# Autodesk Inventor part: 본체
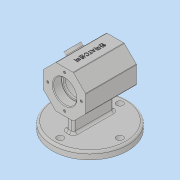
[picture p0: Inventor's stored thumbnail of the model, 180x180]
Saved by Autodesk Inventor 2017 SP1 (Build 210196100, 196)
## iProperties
Part Number: 본체
Material: 일반
Document SubType Name: Modeling
Designer: 00-00
Density: 1 g/cm^3
Appearance: 기본값
Author: 00-00
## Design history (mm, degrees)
sketch "스케치1" dims "d0" = 58
  geometry: L1 (12.012, 29)-(29, 12.012); L2 (29, 12.012)-(29, -12.012); L3 (29, -12.012)-(12.012, -29); L4 (12.012, -29)-(-12.012, -29); L5 (-12.012, -29)-(-29, -12.012); L6 (-29, -12.012)-(-29, 12.012); L7 (-29, 12.012)-(-12.012, 29); L8 (-12.012, 29)-(12.012, 29); 4 further points
  constraints: 16 end point, 2 coincident, 2 vertical alignment, 1 midpoint, 19 other
extrude "돌출1" new body sketch "스케치1" stored distance "d1" = 70; taper "d2" = 0 deg
sketch "스케치2"
  geometry: L1 (29, -35)-(-29, -35) reference; L2 (-29, -35)-(-29, 35) reference; L3 (-29, 35)-(29, 35) reference; L4 (29, 35)-(29, -35) reference; L5 (0, 35)-(16, 35); L6 (16, 35)-(16, 23); L7 (16, 23)-(0, 23); L8 (0, 23)-(0, 35); L9 (0, 23)-(14, 23); L10 (14, 23)-(14, 20); L11 (14, 20)-(0, 20); L12 (0, 20)-(0, 23); L13 (0, 20)-(22, 20); L14 (22, 20)-(22, -20); L15 (22, -20)-(0, -20); L16 (0, -20)-(0, 20); L17 (0, -20)-(14, -20); L18 (14, -20)-(14, -23); L19 (14, -23)-(0, -23); L20 (0, -23)-(0, -20); L21 (0, -23)-(16, -23); L22 (16, -23)-(16, -35); L23 (16, -35)-(0, -35); L24 (0, -35)-(0, -23); 2 further points
  constraints: 40 end point, 10 parallel, 5 horizontal, 5 perpendicular, 2 midpoint, 1 horizontal alignment, 1 point on line
  dimensions: "d3" = 32 diameter of L6 L8; "d4" = 40 distance of L13.end L14.end; "d5" = 12 distance of L5.end L6.end; "d6" = 12 distance of L21.end L22.end; "d7" = 44 diameter of L14 L16; "d8" = 32 diameter of L22 L24; "d9" = 28 diameter of L18 L20; "d10" = 28 diameter of L10 L12
revolve "회전1" sketch "스케치2" stored, may be unused: angle "d11" = 90 deg
chamfer "모따기1" distance "d12" = 1; stored, may be unused: second distance "d13" = 2, angle "d14" = 45 deg
fillet "모깎기1" dims "d15" = 0.3
fillet "모깎기2" dims "d16" = 3
node "작업 평면1"
sketch "스케치3"
  geometry: C1 r 52 at (0, 0); 1 further point
  constraints: 1 centre point, 1 coincident
  dimensions: "d18" = 104 diameter of C1
extrude "돌출2" join sketch "스케치3" distance "d19" = 10; taper "d20" = 0 deg
sketch "스케치4"
  geometry: L1 (-5, -28)-(5, -28); L2 (5, -28)-(5, 28); L3 (5, 28)-(-5, 28); L4 (-5, 28)-(-5, -28); 3 further points
  constraints: 8 end point, 2 midpoint, 2 parallel, 1 horizontal, 1 horizontal alignment, 1 perpendicular, 1 vertical alignment
  dimensions: "d21" = 10 distance of L2.end L3.end; "d22" = 56 distance of L3.end L1.start
extrude "돌출3" join sketch "스케치4" stored distance "d23" = 10; taper "d24" = 0 deg
sketch "스케치5"
  geometry: L1 (-5, -28)-(-5, 28) reference; L2 (-5, 28)-(5, 28) reference; L3 (5, 28)-(5, -28) reference; L4 (5, -28)-(-5, -28) reference; C1 r 52 at (0, 0) reference; 2 further points
  constraints: 1 horizontal alignment
  dimensions: "d26" = 41 distance of point (0, 0) point (-41, 0)
hole "구멍1" sketch "스케치5" at (-41, 0) diameter "d27" = 9; stored, may be unused: countersink angle "d31" = 90 deg, drill point angle "d33" = 0 deg; dims "d28" = 6, "d29" = 4, "d30" = 2, "d32" = 8
fillet "모깎기3" dims "d37" = 3
fillet "모깎기4" dims "d38" = 3
fillet "모깎기5" dims "d39" = 3
fillet "모깎기6" dims "d40" = 3
sketch "스케치6"
  geometry: 2 further points
  constraints: 1 vertical alignment
  dimensions: "d41" = 23 distance of point (0, 0) point (0, -23)
hole "구멍2" sketch "스케치6" at (0, -23) diameter "d42" = 3.242; stored, may be unused: countersink angle "d46" = 90 deg, drill point angle "d48" = 118 deg; dims "d43" = 8, "d44" = 4, "d45" = 2, "d47" = 10
fillet "모깎기7" dims "d52" = 1
node "작업 평면2"
sketch "스케치8"
  geometry: C1 r 10 at (-11.598, 35); 1 further point
  constraints: 1 centre point, 1 coincident
  dimensions: "d54" = 20 diameter of C1
extrude "돌출4" join sketch "스케치8" stored distance "d55" = 10; taper "d56" = 0 deg
sketch "스케치9"
  geometry: C1 r 8 at (0, 0); 1 further point
  constraints: 1 centre point, 1 coincident
  dimensions: "d57" = 16 diameter of C1
extrude "돌출5" cut sketch "스케치9" distance "d58" = 2; taper "d59" = 0 deg
sketch "스케치10"
  geometry: 2 further points
  constraints: 1 coincident
hole "구멍3" sketch "스케치10" at (0, 0) diameter "d60" = 10.917; stored, may be unused: countersink angle "d64" = 90 deg, drill point angle "d66" = 0 deg; dims "d61" = 50, "d62" = 4, "d63" = 2, "d65" = 29.1
chamfer "모따기2" distance "d67" = 1; stored, may be unused: second distance "d68" = 2, angle "d69" = 45 deg
fillet "모깎기8" dims "d70" = 1
sketch "스케치11"
  geometry: L1 (23.196, -70)-(0, -70) reference; 3 further points; 1 other entity
  constraints: 1 coincident, 2 other
  dimensions: "d71" = 35 distance from line of point (11.598, -35) L1 (derived)
feature "엠보싱1" sketch "스케치11" dims "d72" = 0.5, "d73" = 0
node "솔리드1"
pattern_circular "원형 패턴1" dims angle "d35" = 360 deg
pattern_circular "원형 패턴2" dims angle "d50" = 360 deg
mirror "미러1"
node "절단 모서리 투영1"
node "절단 모서리 투영2"
other parameters: "d17" = 62, "d53" = 5
